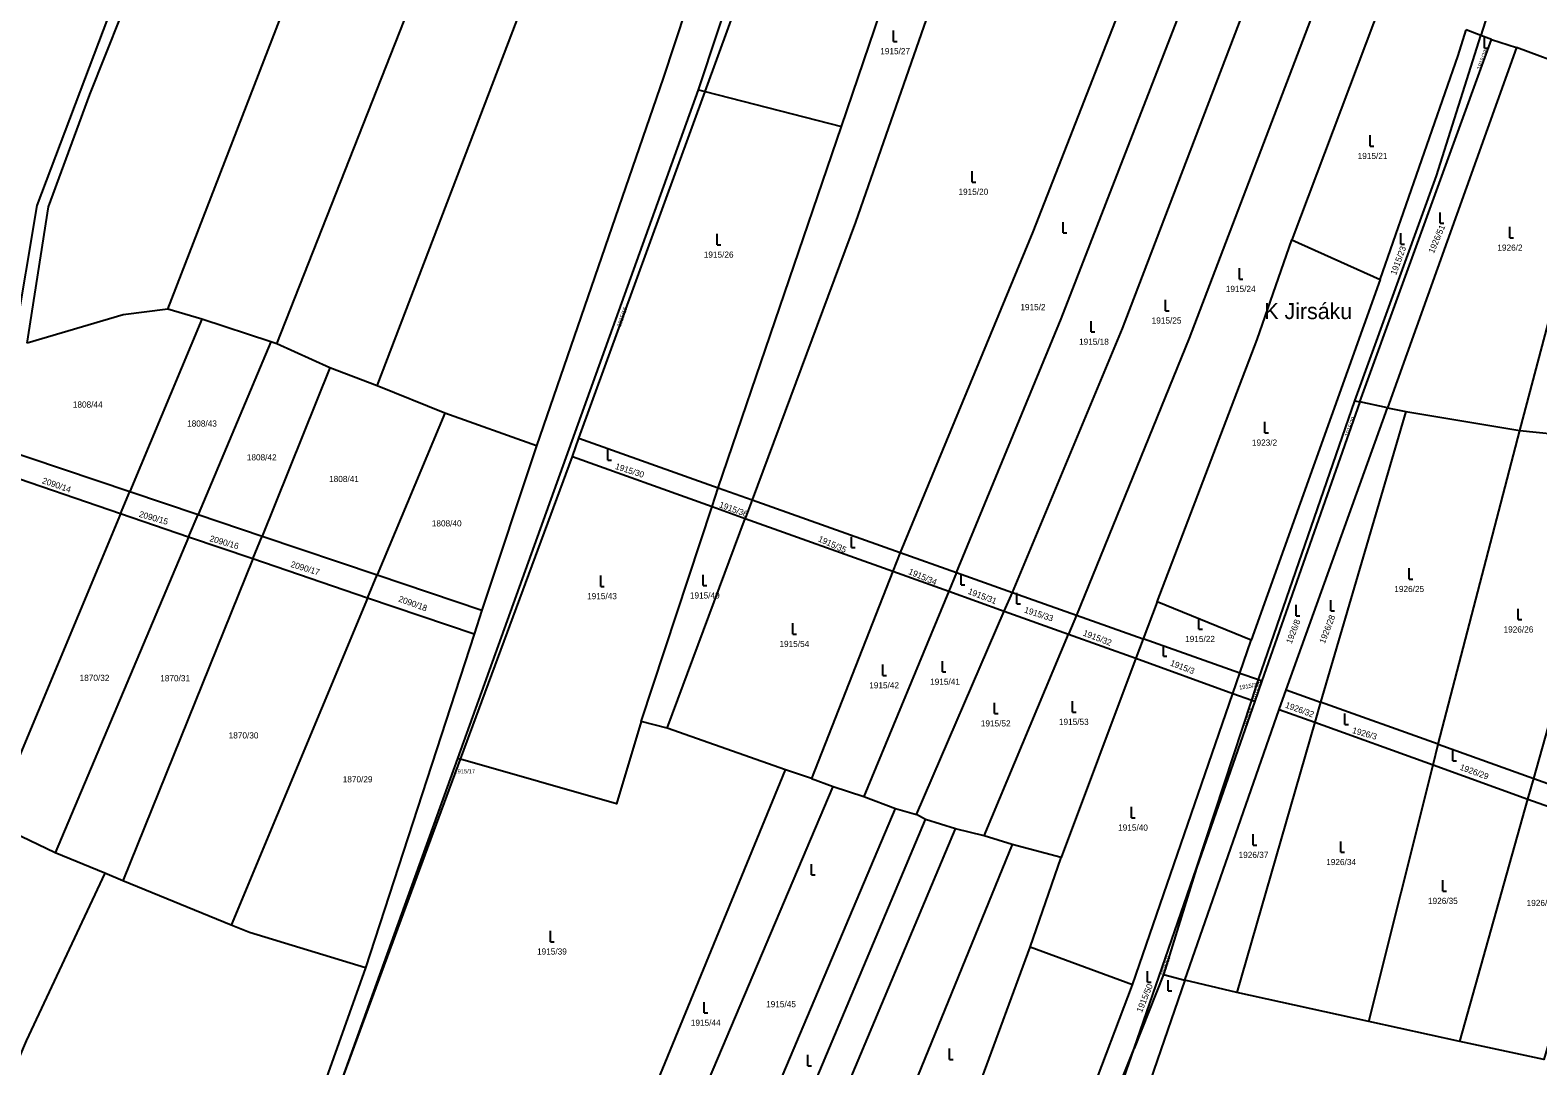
# Model space of a CAD drawing. Extents: x -679220 to -673243, y -1075091 to -1066557.
# Drawn here: x -677359.8 to -676943.8, y -1073777.3 to -1073491.5 of the extents above; entities that cross this region are included whole.
import ezdxf

# ---------------------------------------------------------------- set-up
doc = ezdxf.new("R2010")
doc.units = 0
for name, color, linetype in [('Hranice parcel', 7, 'Continuous'), ('Parcelní čísla', 7, 'Continuous'), ('Pop  PČ popisy', 7, 'Continuous'), ('Značky kultur', 7, 'Continuous')]:
    doc.layers.add(name, color=color, linetype=linetype)

msp = doc.modelspace()

# ---------------------------------------------------------------- linework, layer by layer
at = {"layer": 'Hranice parcel'}
for p, q in [((-677135.9, -1073518.11), (-677109.46, -1073440.06)), ((-676986.73, -1073483.26), (-677011.63, -1073549.35)), ((-676959.5, -1073492.95), (-676963.61, -1073491.41)), ((-676992.94, -1073594.05), (-676956.6, -1073494.04)), ((-676949.69, -1073496.31), (-676985.31, -1073595.69)), ((-676956.6, -1073494.04), (-676959.5, -1073492.95)), ((-676956.6, -1073494.04), (-676949.69, -1073496.31)), ((-676923.48, -1073506.06), (-676949.69, -1073496.31)), ((-677241.79, -1073692.5), (-677175.38, -1073507.95)), ((-677208.4, -1073604.14), (-677173.54, -1073508.42)), ((-677175.38, -1073507.95), (-677173.54, -1073508.42)), ((-677173.54, -1073508.42), (-677135.9, -1073518.11)), ((-676948.75, -1073602.01), (-676923.48, -1073506.06)), ((-677169.95, -1073617.81), (-677135.9, -1073518.11)), ((-677011.63, -1073549.35), (-676987.3, -1073560.31)), ((-676987.3, -1073560.31), (-677022.89, -1073659.88)), ((-677312.39, -1073571.25), (-677332.26, -1073618.82)), ((-677312.39, -1073571.25), (-677321.8, -1073568.47)), ((-677293.34, -1073577.55), (-677312.39, -1073571.25)), ((-677293.34, -1073577.55), (-677313.43, -1073625.17)), ((-677291.67, -1073578.1), (-677293.34, -1073577.55)), ((-677277.08, -1073584.71), (-677291.67, -1073578.1)), ((-677277.08, -1073584.71), (-677295.8, -1073631.11)), ((-677264.06, -1073589.62), (-677277.08, -1073584.71)), ((-677245.39, -1073597.2), (-677264.06, -1073589.62)), ((-677020.89, -1073670.73), (-676994.3, -1073593.76)), ((-676992.94, -1073594.05), (-677019.99, -1073671.05)), ((-677013.24, -1073673.59), (-676985.31, -1073595.69)), ((-676980.23, -1073596.78), (-677003.73, -1073676.99)), ((-676994.3, -1073593.76), (-676992.94, -1073594.05)), ((-676985.31, -1073595.69), (-676992.94, -1073594.05)), ((-676985.31, -1073595.69), (-676980.23, -1073596.78)), ((-676980.23, -1073596.78), (-676948.75, -1073602.01)), ((-677245.39, -1073597.2), (-677264, -1073641.83)), ((-677220.1, -1073606.23), (-677245.39, -1073597.2)), ((-677210.17, -1073609.17), (-677208.4, -1073604.14)), ((-677208.4, -1073604.14), (-677169.95, -1073617.81)), ((-676971.27, -1073688.58), (-676948.75, -1073602.01)), ((-676948.75, -1073602.01), (-676928.07, -1073604.12)), ((-676944.93, -1073697.99), (-676918.77, -1073604.86)), ((-677371.77, -1073605.5), (-677332.26, -1073618.82)), ((-677241.02, -1073692.72), (-677210.17, -1073609.17)), ((-677220.1, -1073606.23), (-677235.14, -1073651.56)), ((-677210.17, -1073609.17), (-677171.61, -1073622.97)), ((-677334.83, -1073624.98), (-677374.21, -1073611.53)), ((-677334.83, -1073624.98), (-677332.26, -1073618.82)), ((-677332.26, -1073618.82), (-677313.43, -1073625.17)), ((-677171.61, -1073622.97), (-677169.95, -1073617.81)), ((-677169.95, -1073617.81), (-677160.6, -1073621.14)), ((-677160.6, -1073621.14), (-677162.49, -1073626.24)), ((-677160.6, -1073621.14), (-677119.75, -1073635.67)), ((-677334.83, -1073624.98), (-677370.39, -1073710.1)), ((-677316.06, -1073631.39), (-677334.83, -1073624.98)), ((-677316.06, -1073631.39), (-677313.43, -1073625.17)), ((-677313.43, -1073625.17), (-677295.8, -1073631.11)), ((-677191.16, -1073682.25), (-677171.61, -1073622.97)), ((-677171.61, -1073622.97), (-677162.49, -1073626.24)), ((-677184.05, -1073684.13), (-677162.49, -1073626.24)), ((-677162.49, -1073626.24), (-677121.76, -1073640.82)), ((-677316.06, -1073631.39), (-677352.83, -1073718.57)), ((-677298.35, -1073637.44), (-677316.06, -1073631.39)), ((-677298.35, -1073637.44), (-677295.8, -1073631.11)), ((-677295.8, -1073631.11), (-677264, -1073641.83)), ((-677298.35, -1073637.44), (-677334.16, -1073726.22)), ((-677266.68, -1073648.25), (-677298.35, -1073637.44)), ((-677119.75, -1073635.67), (-677121.76, -1073640.82)), ((-677119.75, -1073635.67), (-677104.23, -1073641.19)), ((-677266.68, -1073648.25), (-677264, -1073641.83)), ((-677264, -1073641.83), (-677235.14, -1073651.56)), ((-677121.76, -1073640.82), (-677144.18, -1073698.03)), ((-677121.76, -1073640.82), (-677106.35, -1073646.33)), ((-677104.23, -1073641.19), (-677106.35, -1073646.33)), ((-677104.23, -1073641.19), (-677088.78, -1073646.69)), ((-677106.35, -1073646.33), (-677129.74, -1073703.03)), ((-677106.35, -1073646.33), (-677091, -1073651.82)), ((-677091, -1073651.82), (-677088.78, -1073646.69)), ((-677088.78, -1073646.69), (-677071.09, -1073652.98)), ((-677266.68, -1073648.25), (-677304.3, -1073738.47)), ((-677237.26, -1073658.18), (-677266.68, -1073648.25)), ((-677048.85, -1073649.24), (-677052.7, -1073659.52)), ((-677022.89, -1073659.88), (-677048.85, -1073649.24)), ((-677235.14, -1073651.56), (-677237.26, -1073658.18)), ((-677115.24, -1073707.98), (-677091, -1073651.82)), ((-677091, -1073651.82), (-677073.27, -1073658.17)), ((-677071.09, -1073652.98), (-677073.27, -1073658.17)), ((-677071.09, -1073652.98), (-677052.7, -1073659.52)), ((-677237.26, -1073658.18), (-677267.25, -1073750.24)), ((-677096.54, -1073713.87), (-677073.27, -1073658.17)), ((-677073.27, -1073658.17), (-677054.69, -1073664.82)), ((-677052.7, -1073659.52), (-677054.69, -1073664.82)), ((-677026.01, -1073668.93), (-677052.7, -1073659.52)), ((-677026.01, -1073668.93), (-677022.89, -1073659.88)), ((-677054.69, -1073664.82), (-677075.27, -1073719.8)), ((-677054.69, -1073664.82), (-677027.94, -1073674.52)), ((-677027.94, -1073674.52), (-677026.01, -1073668.93)), ((-677026.01, -1073668.93), (-677020.89, -1073670.73)), ((-677022.75, -1073676.39), (-677020.89, -1073670.73)), ((-677019.99, -1073671.05), (-677021.88, -1073676.71)), ((-677020.89, -1073670.73), (-677019.99, -1073671.05)), ((-677055.68, -1073754.95), (-677027.94, -1073674.52)), ((-677027.94, -1073674.52), (-677022.75, -1073676.39)), ((-677015.2, -1073678.94), (-677013.24, -1073673.59)), ((-677013.24, -1073673.59), (-677003.73, -1073676.99)), ((-677041.18, -1073753.69), (-677015.2, -1073678.94)), ((-677038.01, -1073722.76), (-677022.75, -1073676.39)), ((-677021.88, -1073676.71), (-677038.01, -1073722.76)), ((-677022.75, -1073676.39), (-677021.88, -1073676.71)), ((-677015.2, -1073678.94), (-677005.34, -1073682.49)), ((-677003.73, -1073676.99), (-677005.34, -1073682.49)), ((-676971.27, -1073688.58), (-677003.73, -1073676.99)), ((-677184.05, -1073684.13), (-677191.16, -1073682.25)), ((-677151.41, -1073695.65), (-677184.05, -1073684.13)), ((-677005.34, -1073682.49), (-677026.85, -1073757.03)), ((-677005.34, -1073682.49), (-676972.69, -1073694.27)), ((-677274.67, -1073783.86), (-677241.79, -1073692.5)), ((-677241.79, -1073692.5), (-677241.02, -1073692.72)), ((-676972.69, -1073694.27), (-676971.27, -1073688.58)), ((-676971.27, -1073688.58), (-676944.93, -1073697.99)), ((-677274.67, -1073783.86), (-677241.02, -1073692.72)), ((-677198.81, -1073811.08), (-677151.41, -1073695.65)), ((-677144.18, -1073698.03), (-677151.41, -1073695.65)), ((-676990.4, -1073765.04), (-676972.69, -1073694.27)), ((-676972.69, -1073694.27), (-676946.54, -1073703.7)), ((-677187.02, -1073815.31), (-677138.22, -1073700.25)), ((-677144.18, -1073698.03), (-677138.22, -1073700.25)), ((-677138.22, -1073700.25), (-677129.74, -1073703.03)), ((-676946.54, -1073703.7), (-676944.93, -1073697.99)), ((-676944.93, -1073697.99), (-676920.93, -1073706.56)), ((-677129.74, -1073703.03), (-677121.05, -1073706.31)), ((-676965.34, -1073770.62), (-676946.54, -1073703.7)), ((-676946.54, -1073703.7), (-676922.79, -1073712.26)), ((-677169.79, -1073821.49), (-677121.05, -1073706.31)), ((-677121.05, -1073706.31), (-677115.24, -1073707.98)), ((-677112.77, -1073709.3), (-677115.24, -1073707.98)), ((-677352.83, -1073718.57), (-677370.39, -1073710.1)), ((-677161.19, -1073824.57), (-677112.77, -1073709.3)), ((-677153.03, -1073827.5), (-677104.48, -1073711.89)), ((-677104.48, -1073711.89), (-677112.77, -1073709.3)), ((-677096.54, -1073713.87), (-677104.48, -1073711.89)), ((-677088.87, -1073716.25), (-677136.62, -1073833.39)), ((-677088.87, -1073716.25), (-677096.54, -1073713.87)), ((-677075.27, -1073719.8), (-677088.87, -1073716.25)), ((-677339.15, -1073724.18), (-677352.83, -1073718.57)), ((-677083.9, -1073744.58), (-677075.27, -1073719.8)), ((-677334.16, -1073726.22), (-677339.15, -1073724.18)), ((-677055.2, -1073772.5), (-677038.01, -1073722.76)), ((-677038.01, -1073722.76), (-677047.07, -1073752.1)), ((-677304.3, -1073738.47), (-677334.16, -1073726.22)), ((-677055.68, -1073754.95), (-677083.9, -1073744.58)), ((-677041.18, -1073753.69), (-677076.2, -1073855.05)), ((-677047.07, -1073752.1), (-677055.2, -1073772.5)), ((-677047.07, -1073752.1), (-677041.18, -1073753.69)), ((-677026.85, -1073757.03), (-677041.18, -1073753.69)), ((-677087.55, -1073839.44), (-677055.68, -1073754.95)), ((-676990.4, -1073765.04), (-677026.85, -1073757.03)), ((-676965.34, -1073770.62), (-676990.4, -1073765.04)), ((-677082.9, -1073852.66), (-677055.2, -1073772.5))]:
    msp.add_line(p, q, dxfattribs=at)
for points in [[(-677360.6, -1073577.91), (-677354.7, -1073540.24), (-677343.27, -1073509.23), (-677334.63, -1073487.55), (-677322.3, -1073460.58), (-677308.99, -1073413.79), (-677290.91, -1073370.83), (-677252.83, -1073268.54), (-677233.44, -1073217.39), (-677224.14, -1073188.44), (-677213.31, -1073160.11)], [(-677264.06, -1073589.62), (-677224.22, -1073485.56), (-677210.76, -1073442.48), (-677188.66, -1073381.24), (-677167.66, -1073319.59), (-677126.89, -1073197.06)], [(-677086.62, -1073206.07), (-677121.07, -1073312.55), (-677140.62, -1073369.77), (-677185.1, -1073504.75), (-677220.1, -1073606.23)], [(-677175.38, -1073507.95), (-677127.23, -1073362.44), (-677111.23, -1073315.22), (-677109.49, -1073308.79)], [(-676898.91, -1073306.59), (-676912.58, -1073344.63), (-676959.5, -1073492.95)], [(-677321.8, -1073568.47), (-677277.3, -1073453.37), (-677282.04, -1073451.73), (-677253.25, -1073378.52)], [(-677291.67, -1073578.1), (-677245.31, -1073460.16), (-677248.85, -1073458.52), (-677223.81, -1073389.26)], [(-677173.54, -1073508.42), (-677144.2, -1073427.83), (-677109.46, -1073440.06)], [(-677097.17, -1073444.38), (-677132.03, -1073544.52), (-677160.6, -1073621.14)], [(-677325.02, -1073459.98), (-677338.32, -1073488.07), (-677357.95, -1073539.92), (-677364.05, -1073576.72), (-677375.09, -1073604.38)], [(-677049.58, -1073461.14), (-677083.15, -1073547.2), (-677119.75, -1073635.67)], [(-677104.23, -1073641.19), (-677075.32, -1073571.14), (-677034.69, -1073466.38)], [(-677088.78, -1073646.69), (-677058.36, -1073573.83), (-677019.37, -1073471.77)], [(-677002.43, -1073477.73), (-677039.97, -1073576.48), (-677071.09, -1073652.98)], [(-676987.3, -1073560.31), (-676965.75, -1073498.5), (-676963.61, -1073491.41)], [(-676994.3, -1073593.76), (-676971.78, -1073531.71), (-676959.5, -1073492.95)], [(-677048.85, -1073649.24), (-677021.2, -1073576.85), (-677011.63, -1073549.35)], [(-677321.8, -1073568.47), (-677334.07, -1073570.04), (-677360.6, -1073577.91)], [(-677191.16, -1073682.25), (-677198, -1073704.98), (-677241.02, -1073692.72)], [(-677339.15, -1073724.18), (-677360.83, -1073770.42), (-677402.15, -1073867.25)], [(-676931.14, -1073737.92), (-676942.14, -1073775.54), (-676965.34, -1073770.62)], [(-677267.25, -1073750.24), (-677299.27, -1073740.53), (-677304.3, -1073738.47)], [(-677117.63, -1073828.57), (-677097.75, -1073782.27), (-677083.9, -1073744.58)], [(-677267.25, -1073750.24), (-677277.56, -1073779.28), (-677299.42, -1073841.1), (-677325.97, -1073912.16)], [(-677085.87, -1073851.59), (-677066.77, -1073801.54), (-677055.2, -1073772.5)]]:
    msp.add_lwpolyline(points, dxfattribs=at)
at = {"layer": 'Značky kultur'}
for p, q in [((-677121.53, -1073494.6), (-677121.53, -1073491.6)), ((-677121.53, -1073494.6), (-677120.53, -1073494.6)), ((-676958.48, -1073496.51), (-676958.48, -1073493.51)), ((-676958.48, -1073496.51), (-676957.48, -1073496.51)), ((-676990.08, -1073523.52), (-676990.08, -1073520.52)), ((-676990.08, -1073523.52), (-676989.08, -1073523.52)), ((-677099.89, -1073533.41), (-677099.89, -1073530.41)), ((-677099.89, -1073533.41), (-677098.89, -1073533.41)), ((-676970.71, -1073544.8), (-676970.71, -1073541.8)), ((-677074.76, -1073547.46), (-677074.76, -1073544.46)), ((-676970.71, -1073544.8), (-676969.71, -1073544.8)), ((-676951.51, -1073548.82), (-676951.51, -1073545.82)), ((-677170.18, -1073550.75), (-677170.18, -1073547.75)), ((-677170.18, -1073550.75), (-677169.18, -1073550.75)), ((-677074.76, -1073547.46), (-677073.76, -1073547.46)), ((-676981.62, -1073550.54), (-676981.62, -1073547.54)), ((-676981.62, -1073550.54), (-676980.62, -1073550.54)), ((-676951.51, -1073548.82), (-676950.51, -1073548.82)), ((-677026.15, -1073560.21), (-677026.15, -1073557.21)), ((-677026.15, -1073560.21), (-677025.15, -1073560.21)), ((-677046.56, -1073568.93), (-677046.56, -1073565.93)), ((-677067, -1073574.78), (-677067, -1073571.78)), ((-677046.56, -1073568.93), (-677045.56, -1073568.93)), ((-677067, -1073574.78), (-677066, -1073574.78)), ((-677019.14, -1073602.62), (-677019.14, -1073599.62)), ((-677019.14, -1073602.62), (-677018.14, -1073602.62)), ((-677200.36, -1073610.14), (-677200.36, -1073607.14)), ((-677200.36, -1073610.14), (-677199.36, -1073610.14)), ((-677133.16, -1073634.31), (-677133.16, -1073631.31)), ((-677133.16, -1073634.31), (-677132.16, -1073634.31)), ((-677202.36, -1073644.99), (-677202.36, -1073641.99)), ((-677174.08, -1073644.8), (-677174.08, -1073641.8)), ((-677102.91, -1073644.53), (-677102.91, -1073641.53)), ((-676979.29, -1073643.02), (-676979.29, -1073640.02)), ((-677202.36, -1073644.99), (-677201.36, -1073644.99)), ((-677174.08, -1073644.8), (-677173.08, -1073644.8)), ((-677102.91, -1073644.53), (-677101.91, -1073644.53)), ((-677087.51, -1073649.79), (-677087.51, -1073646.79)), ((-676979.29, -1073643.02), (-676978.29, -1073643.02)), ((-677087.51, -1073649.79), (-677086.51, -1073649.79)), ((-677010.5, -1073653.09), (-677010.5, -1073650.09)), ((-677000.9, -1073651.77), (-677000.9, -1073648.77)), ((-677037.31, -1073656.81), (-677037.31, -1073653.81)), ((-677010.5, -1073653.09), (-677009.5, -1073653.09)), ((-677000.9, -1073651.77), (-676999.9, -1073651.77)), ((-676949.19, -1073654.18), (-676949.19, -1073651.18)), ((-676949.19, -1073654.18), (-676948.19, -1073654.18)), ((-677149.33, -1073658.18), (-677149.33, -1073655.18)), ((-677149.33, -1073658.18), (-677148.33, -1073658.18)), ((-677037.31, -1073656.81), (-677036.31, -1073656.81)), ((-677047.12, -1073664.3), (-677047.12, -1073661.3)), ((-677124.53, -1073669.6), (-677124.53, -1073666.6)), ((-677108.1, -1073668.61), (-677108.1, -1073665.61)), ((-677047.12, -1073664.3), (-677046.12, -1073664.3)), ((-677124.53, -1073669.6), (-677123.53, -1073669.6)), ((-677108.1, -1073668.61), (-677107.1, -1073668.61)), ((-677093.7, -1073680.11), (-677093.7, -1073677.11)), ((-677072.15, -1073679.68), (-677072.15, -1073676.68)), ((-677072.15, -1073679.68), (-677071.15, -1073679.68)), ((-677093.7, -1073680.11), (-677092.7, -1073680.11)), ((-676997.08, -1073683.1), (-676997.08, -1073680.1)), ((-676997.08, -1073683.1), (-676996.08, -1073683.1)), ((-676967.25, -1073693.11), (-676967.25, -1073690.11)), ((-676967.25, -1073693.11), (-676966.25, -1073693.11)), ((-677055.9, -1073708.86), (-677055.9, -1073705.86)), ((-677055.9, -1073708.86), (-677054.9, -1073708.86)), ((-677022.32, -1073716.39), (-677022.32, -1073713.39)), ((-677022.32, -1073716.39), (-677021.32, -1073716.39)), ((-676998.11, -1073718.37), (-676998.11, -1073715.37)), ((-677144.2, -1073724.64), (-677144.2, -1073721.64)), ((-676998.11, -1073718.37), (-676997.11, -1073718.37)), ((-677144.2, -1073724.64), (-677143.2, -1073724.64)), ((-676969.99, -1073729.09), (-676969.99, -1073726.09)), ((-676969.99, -1073729.09), (-676968.99, -1073729.09)), ((-677216.17, -1073743.06), (-677216.17, -1073740.06)), ((-677216.17, -1073743.06), (-677215.17, -1073743.06)), ((-677051.52, -1073754.22), (-677051.52, -1073751.22)), ((-677051.52, -1073754.22), (-677050.52, -1073754.22)), ((-677045.79, -1073756.63), (-677045.79, -1073753.63)), ((-677045.79, -1073756.63), (-677044.79, -1073756.63)), ((-677173.82, -1073762.7), (-677173.82, -1073759.7)), ((-677173.82, -1073762.7), (-677172.82, -1073762.7)), ((-677145.21, -1073777.3), (-677145.21, -1073774.3)), ((-677106.08, -1073775.57), (-677106.08, -1073772.57)), ((-677106.08, -1073775.57), (-677105.08, -1073775.57)), ((-677145.21, -1073777.3), (-677144.21, -1073777.3))]:
    msp.add_line(p, q, dxfattribs=at)

# ---------------------------------------------------------------- texts
at = {"layer": 'Parcelní čísla'}
for s, height, p in [('1915/27', 1.7, (-677125.23, -1073498.15)), ('1915/21', 1.7, (-676993.51, -1073527.07)), ('1915/20', 1.7, (-677103.65, -1073536.96)), ('1926/2', 1.7, (-676954.97, -1073552.37)), ('1915/26', 1.7, (-677173.92, -1073554.3)), ('1915/24', 1.7, (-677029.89, -1073563.76)), ('1915/2', 1.7, (-677086.57, -1073568.78)), ('1915/25', 1.7, (-677050.34, -1073572.48)), ('1915/18', 1.7, (-677070.38, -1073578.33)), ('1808/44', 1.7, (-677347.99, -1073595.67)), ('1808/43', 1.7, (-677316.47, -1073600.91)), ('1923/2', 1.7, (-677022.68, -1073606.17)), ('1808/42', 1.7, (-677299.99, -1073610.24)), ('1808/41', 1.7, (-677277.29, -1073616.21)), ('1808/40', 1.7, (-677248.95, -1073628.46)), ('1915/43', 1.7, (-677206.11, -1073648.54)), ('1915/49', 1.7, (-677177.75, -1073648.35)), ('1926/25', 1.7, (-676983.4, -1073646.57)), ('1915/22', 1.7, (-677041.11, -1073660.36)), ('1926/26', 1.7, (-676953.26, -1073657.73)), ('1915/54', 1.7, (-677153.04, -1073661.73)), ('1870/32', 1.7, (-677346.12, -1073671.09)), ('1870/31', 1.7, (-677323.88, -1073671.19)), ('1915/42', 1.7, (-677128.27, -1073673.15)), ('1915/41', 1.7, (-677111.47, -1073672.16)), ('1915/52', 1.7, (-677097.48, -1073683.66)), ('1915/53', 1.7, (-677075.94, -1073683.23)), ('1870/30', 1.7, (-677305, -1073686.97)), ('1915/17', 1.14, (-677242.71, -1073696.6)), ('1870/29', 1.7, (-677273.53, -1073699.09)), ('1915/40', 1.7, (-677059.6, -1073712.41)), ('1926/37', 1.7, (-677026.36, -1073719.94)), ('1926/34', 1.7, (-677002.19, -1073721.92)), ('1926/35', 1.7, (-676974.11, -1073732.64)), ('1926/36', 1.7, (-676946.89, -1073733.21)), ('1915/39', 1.7, (-677219.92, -1073746.61)), ('1915/45', 1.7, (-677156.72, -1073761.14)), ('1915/44', 1.7, (-677177.49, -1073766.25))]:
    msp.add_text(s, height=height, dxfattribs=at).set_placement(p)
for s, height, rotation, p in [('1915/28', 1.14, 69, (-676959.61, -1073502.54)), ('1926/51', 1.7, 67, (-676972.51, -1073553.25)), ('1915/23', 1.7, 70, (-676982.92, -1073559.24)), ('1915/16', 1.14, 71, (-677196.83, -1073573.52)), ('1915/29', 1.14, 71, (-676995.97, -1073603.83)), ('1915/30', 1.7, 342, (-677198.52, -1073612.55)), ('2090/14', 1.7, 341, (-677356.61, -1073616.5)), ('1915/36', 1.7, 340, (-677169.83, -1073623.12)), ('2090/15', 1.7, 344, (-677329.89, -1073625.78)), ('2090/16', 1.7, 344, (-677310.4, -1073632.51)), ('1915/35', 1.7, 336, (-677142.53, -1073632.5)), ('2090/17', 1.7, 343, (-677288.05, -1073639.6)), ('1915/34', 1.7, 337, (-677117.62, -1073641.53)), ('1915/31', 1.7, 339, (-677101.18, -1073647.01)), ('2090/18', 1.7, 340, (-677258.32, -1073649.12)), ('1915/33', 1.7, 342, (-677085.65, -1073652.18)), ('1926/8', 1.7, 69, (-677011.75, -1073660.99)), ('1926/28', 1.7, 69, (-677002.59, -1073660.94)), ('1915/32', 1.7, 339, (-677069.45, -1073658.51)), ('1915/3', 1.7, 339, (-677045.4, -1073666.79)), ('1915/37', 1.14, 9, (-677026.12, -1073673.49)), ('1915/38', 1.14, 71, (-677021.52, -1073676.54)), ('1915/55', 1.14, 71, (-677024.18, -1073683.98)), ('1926/32', 1.7, 340, (-677013.66, -1073678.41)), ('1926/3', 1.7, 344, (-676995.15, -1073685.44)), ('1926/29', 1.7, 340, (-676965.48, -1073695.56)), ('1926/50', 1.14, 72, (-677046.88, -1073752.63)), ('1915/50', 1.7, 68, (-677053.05, -1073762.74))]:
    msp.add_text(s, height=height, rotation=rotation, dxfattribs=at).set_placement(p)
at = {"layer": 'Pop  PČ popisy'}
msp.add_text('K Jirsáku', height=4.4, dxfattribs=at).set_placement((-677019.24, -1073571.24))

doc.saveas('drawing.dxf')
